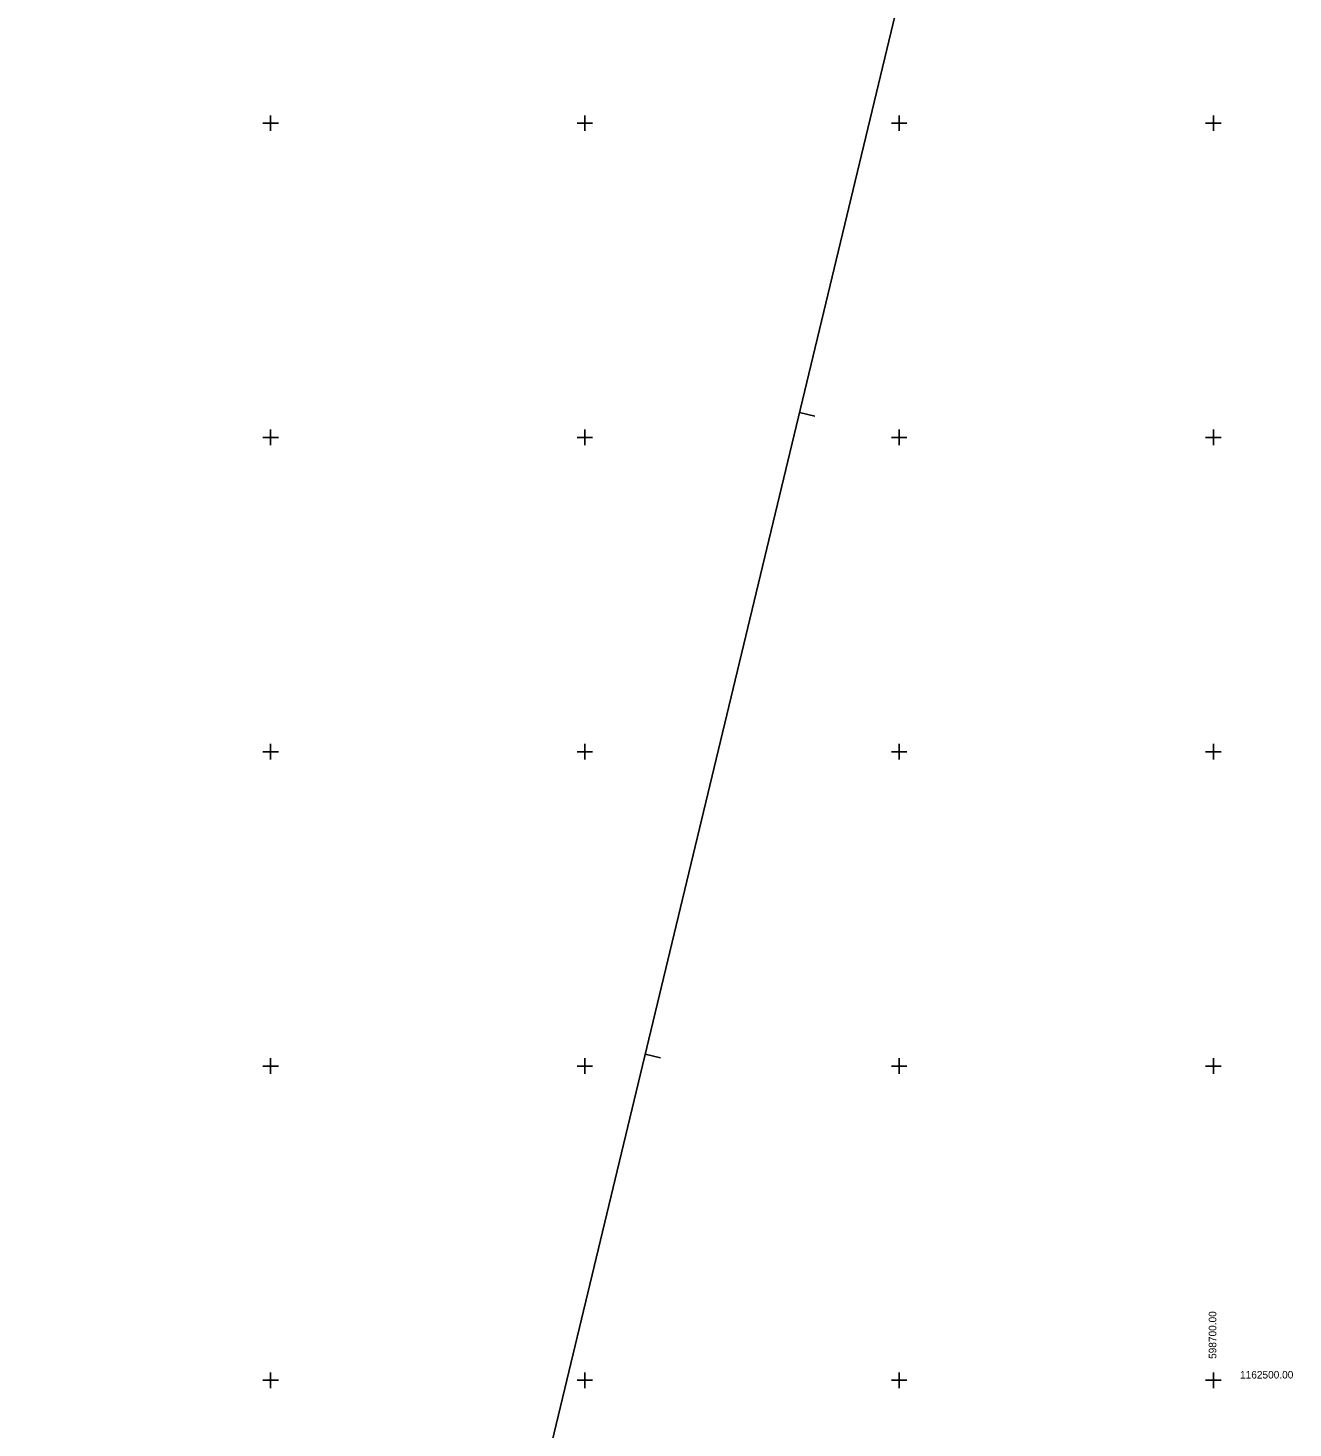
# Model space of a CAD drawing. Extents: x -599151 to -598424, y -1163476 to -1161924.
# Drawn here: x -598794.3 to -598693.7, y -1162503.8 to -1162392.4 of the extents above; entities that cross this region are included whole.
import ezdxf

# ---------------------------------------------------------------- set-up
doc = ezdxf.new("R2010")
doc.units = 0
for name, color, linetype in [('Vrstva 1', 7, 'Continuous'), ('Vrstva 52', 7, 'Continuous'), ('Vrstva 62', 7, 'Continuous')]:
    doc.layers.add(name, color=color, linetype=linetype)

msp = doc.modelspace()

# ---------------------------------------------------------------- linework, layer by layer
at = {"layer": 'Vrstva 1'}
for p, q in [((-598708.37, -1162320.93), (-598794.3, -1162678.24)), ((-598731.71, -1162423.31), (-598732.92, -1162423.02)), ((-598743.98, -1162474.35), (-598745.2, -1162474.06))]:
    msp.add_line(p, q, dxfattribs=at)
at = {"layer": 'Vrstva 62'}
for p, q in [((-598775, -1162400.62), (-598775, -1162399.38)), ((-598750, -1162400.62), (-598750, -1162399.38)), ((-598725, -1162400.62), (-598725, -1162399.38)), ((-598700, -1162400.62), (-598700, -1162399.38)), ((-598775.62, -1162400), (-598774.38, -1162400)), ((-598750.62, -1162400), (-598749.38, -1162400)), ((-598725.62, -1162400), (-598724.38, -1162400)), ((-598700.62, -1162400), (-598699.38, -1162400)), ((-598775.62, -1162425), (-598774.38, -1162425)), ((-598775, -1162425.62), (-598775, -1162424.38)), ((-598750.62, -1162425), (-598749.38, -1162425)), ((-598750, -1162425.62), (-598750, -1162424.38)), ((-598725.62, -1162425), (-598724.38, -1162425)), ((-598725, -1162425.62), (-598725, -1162424.38)), ((-598700.62, -1162425), (-598699.38, -1162425)), ((-598700, -1162425.62), (-598700, -1162424.38)), ((-598775, -1162450.62), (-598775, -1162449.38)), ((-598750, -1162450.62), (-598750, -1162449.38)), ((-598725, -1162450.62), (-598725, -1162449.38)), ((-598700, -1162450.62), (-598700, -1162449.38)), ((-598775.62, -1162450), (-598774.38, -1162450)), ((-598750.62, -1162450), (-598749.38, -1162450)), ((-598725.62, -1162450), (-598724.38, -1162450)), ((-598700.62, -1162450), (-598699.38, -1162450)), ((-598775.62, -1162475), (-598774.38, -1162475)), ((-598775, -1162475.62), (-598775, -1162474.38)), ((-598750.62, -1162475), (-598749.38, -1162475)), ((-598750, -1162475.62), (-598750, -1162474.38)), ((-598725.62, -1162475), (-598724.38, -1162475)), ((-598725, -1162475.62), (-598725, -1162474.38)), ((-598700.62, -1162475), (-598699.38, -1162475)), ((-598700, -1162475.62), (-598700, -1162474.38)), ((-598775, -1162500.62), (-598775, -1162499.38)), ((-598750, -1162500.62), (-598750, -1162499.38)), ((-598725, -1162500.62), (-598725, -1162499.38)), ((-598700, -1162500.62), (-598700, -1162499.38)), ((-598775.62, -1162500), (-598774.38, -1162500)), ((-598750.62, -1162500), (-598749.38, -1162500)), ((-598725.62, -1162500), (-598724.38, -1162500)), ((-598700.62, -1162500), (-598699.38, -1162500))]:
    msp.add_line(p, q, dxfattribs=at)

# ---------------------------------------------------------------- texts
at = {"layer": 'Vrstva 52'}
msp.add_text('598700.00', height=0.6, rotation=90, dxfattribs=at).set_placement((-598699.77, -1162498.3))
msp.add_text('1162500.00', height=0.6, dxfattribs=at).set_placement((-598697.88, -1162499.86))

doc.saveas('drawing.dxf')
